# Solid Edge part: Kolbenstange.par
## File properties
Username: bmolnar
Dokumentum tartalom típus: 0
Author: bmolnar
Last saved by: bmolnar
Revision: 93
Sűrűség: 0,000 kg/m^3
Pontosság: 0,990
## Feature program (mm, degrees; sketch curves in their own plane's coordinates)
base feature "unnamed BaseFeature 1"
thread "unnamed Thread 1"
sketch for "unnamed Protrusion 1" plane through (0, 0, -18.3) normal (0, 0, -1) x-axis (0, -1, 0)
  circle centre (0, 0) radius 10
extrude "unnamed Protrusion 1" add finite 13.4 along +normal
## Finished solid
Body 1: solid body, 17 faces, 23 edges, 8 vertices.
  Faces by surface: plane 8, cylinder 4, torus 3, cone 2
  Edges by curve: circle 13, line 6, ellipse 2, intersection 2
Bounding box of the edges (mm; curved faces can reach further): 20.000 x 20.000 x 172.700, from (-10, -10, -31.7) to (10, 10, 141).
Cylindrical faces by radius (mm): R2.9 x1, R4 x1, R5 x1, R10 x1
Conical faces (half-angle, radius in mm at the cone's reference point): 20 deg R3.5 x1, 60 deg R3.55 x1
Toroidal faces (ring radius, tube radius in mm): R3.3 r0.4 x2, R3.8 r1.2 x1
Planar faces by outward normal: +x 1, +z 3, -x 1, -z 1, oblique 2
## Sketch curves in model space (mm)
circle centre (0, 0, -18.3) radius 10
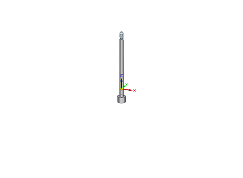
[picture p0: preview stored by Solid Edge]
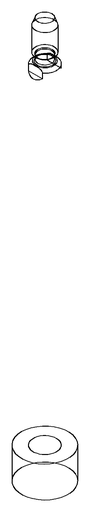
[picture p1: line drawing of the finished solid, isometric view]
